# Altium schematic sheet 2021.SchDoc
size A4
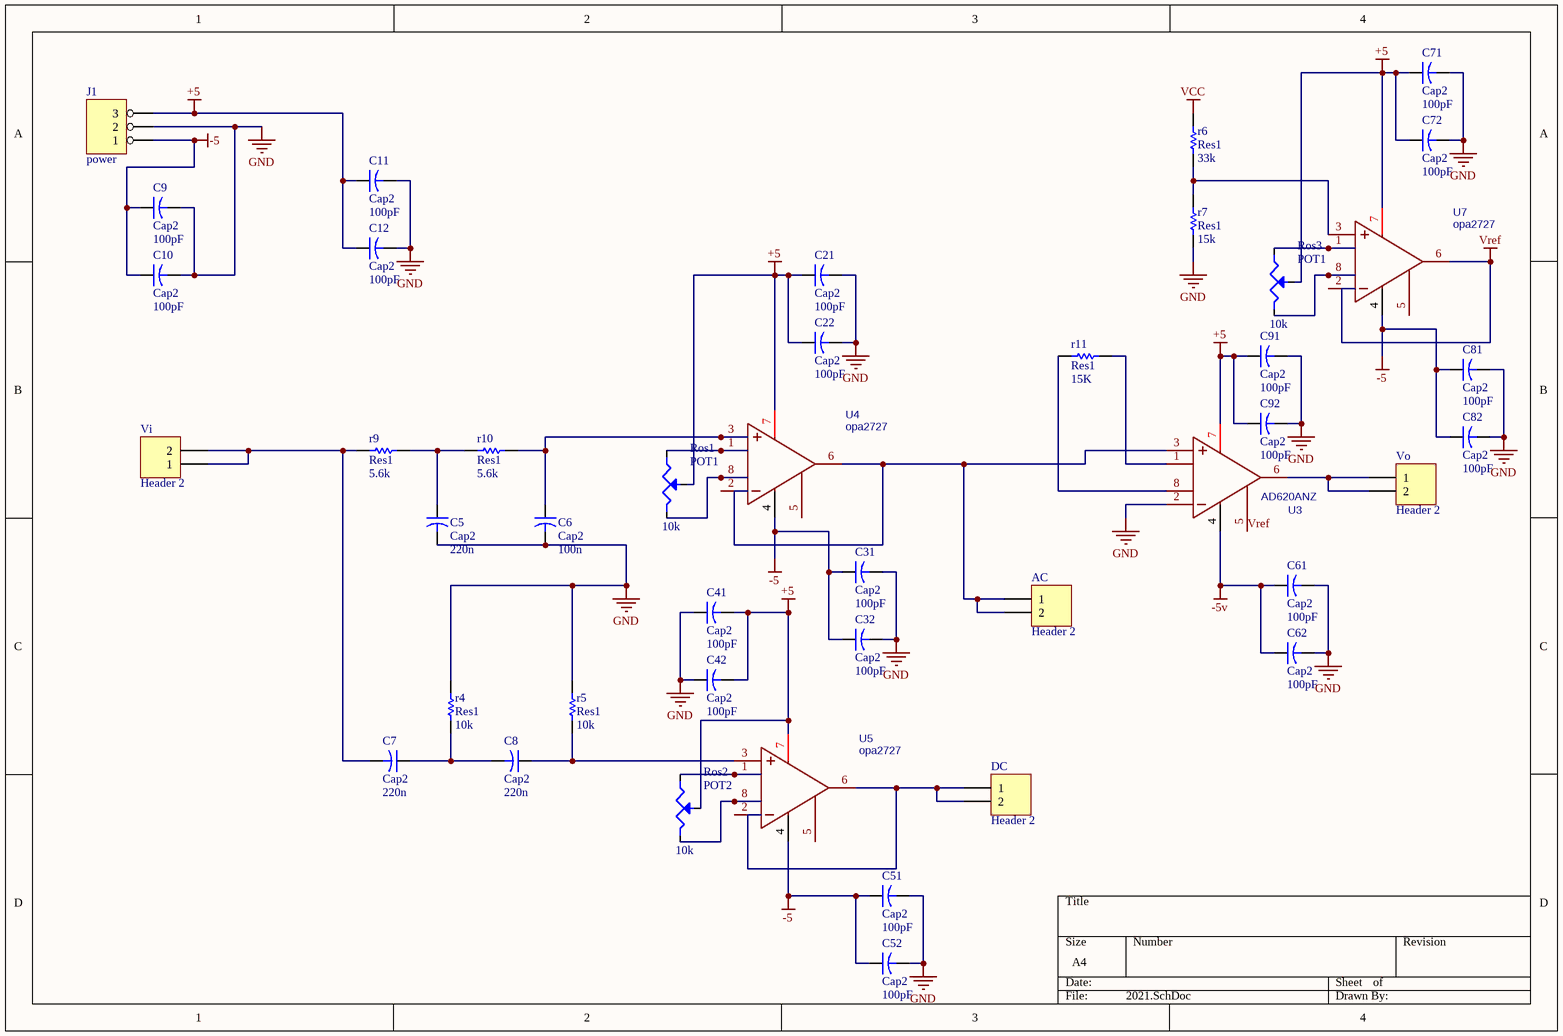
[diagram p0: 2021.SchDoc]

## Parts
AC  Header 2  [HDR1X2]
C5  Cap2  value 220n  [RAD0.2]
C6  Cap2  value 100n  [RAD0.2]
C7  Cap2  value 220n  [RAD0.2]
C8  Cap2  value 220n  [RAD0.2]
C9  Cap2  value 100pF  [RAD0.2]
C10  Cap2  value 100pF  [RAD0.2]
C11  Cap2  value 100pF  [RAD0.2]
C12  Cap2  value 100pF  [RAD0.2]
C21  Cap2  value 100pF  [RAD0.2]
C22  Cap2  value 100pF  [RAD0.2]
C31  Cap2  value 100pF  [RAD0.2]
C32  Cap2  value 100pF  [RAD0.2]
C41  Cap2  value 100pF  [RAD0.2]
C42  Cap2  value 100pF  [RAD0.2]
C51  Cap2  value 100pF  [RAD0.2]
C52  Cap2  value 100pF  [RAD0.2]
C61  Cap2  value 100pF  [RAD0.2]
C62  Cap2  value 100pF  [RAD0.2]
C71  Cap2  value 100pF  [RAD0.2]
C72  Cap2  value 100pF  [RAD0.2]
C81  Cap2  value 100pF  [RAD0.2]
C82  Cap2  value 100pF  [RAD0.2]
C91  Cap2  value 100pF  [RAD0.2]
C92  Cap2  value 100pF  [RAD0.2]
DC  Header 2  [HDR1X2]
J1  power  [SIP3]
r4  Res1  value 10k  [AXIAL-0.3]
r5  Res1  value 10k  [AXIAL-0.3]
r6  Res1  value 33k  [AXIAL-0.3]
r7  Res1  value 15k  [AXIAL-0.3]
r9  Res1  value 5.6k  [AXIAL-0.3]
r10  Res1  value 5.6k  [AXIAL-0.3]
r11  Res1  value 15K  [AXIAL-0.3]
Ros1  POT1  value 10k  [VR5]
Ros2  POT2  value 10k  [VR5]
Ros3  POT1  value 10k  [VR5]
U3  AD620ANZ  [DIP8]
U4  opa2727  [DIP8]
U5  opa2727  [DIP8]
U7  opa2727  [DIP8]
Vi  Header 2  [HDR1X2]
Vo  Header 2  [HDR1X2]

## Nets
+5: C11.1 C12.1 C21.1 C22.1 C41.2 C42.2 C71.1 C72.1 C91.1 C92.1 J1.3 Ros1.3(W) Ros2.3(W) Ros3.3(W) U3.7(+VS) U4.7(+VS) U5.7(+VS) U7.7(+VS)
-5: C9.1 C10.1 C31.1 C32.1 C51.1 C52.1 C81.1 C82.1 J1.1 U4.4(-VS) U5.4(-VS) U7.4(-VS)
-5v: C61.1 C62.1 U3.4(-VS)
GND: C5.2 C6.2 C9.2 C10.2 C11.2 C12.2 C21.2 C22.2 C31.2 C32.2 C41.1 C42.1 C51.2 C52.2 C61.2 C62.2 C71.2 C72.2 C81.2 C82.2 C91.2 C92.2 J1.2 r4.2 r5.2 r7.1 U3.2(-IN)
VCC: r6.2
Vref: U3.5(REF) U7.6(OUTPUT)
NetAC_1: AC.1 AC.2 U3.3(+IN) U4.6(OUTPUT)
NetC5_1: C5.1 r9.2 r10.1
NetC6_1: C6.1 r10.2 U4.3(+IN)
NetC7_1: C7.1 C8.2 r4.1
NetC7_2: C7.2 r9.1 Vi.1 Vi.2
NetC8_1: C8.1 r5.1 U5.3(+IN)
NetDC_1: DC.1 DC.2 U5.6(OUTPUT)
Netr6_1: r6.1 r7.2 U7.3(+IN)
Netr11_1: r11.1 U3.8(RG)
Netr11_2: r11.2 U3.1(RG)
NetRos1_1: Ros1.1 U4.1(RG)
NetRos1_2: Ros1.2 U4.8(RG)
NetRos2_1: Ros2.1 U5.1(RG)
NetRos2_2: Ros2.2 U5.8(RG)
NetRos3_1: Ros3.1 U7.1(RG)
NetRos3_2: Ros3.2 U7.8(RG)
NetU3_6: U3.6(OUTPUT) Vo.1 Vo.2

Not connected (* = marked no-connect by the designer): U4 2(-IN) 5(REF); U5 2(-IN) 5(REF); U7 2(-IN) 5(REF)

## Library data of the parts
AC DC Vi Vo = Header 2: Header, 2-Pin
C5-C12 C21 C22 C31 C32 C41 C42 C51 C52 C61 C62 C71 C72 C81 C82 C91 C92 = Cap2: Capacitor
J1 = HEADER 3
r4-r7 r9-r11 = Res1: Resistor
Ros1-Ros3 = POT1: Potentiometer
U3-U5 U7 = AD620ANZ: BOM_Manufacturer: ADI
